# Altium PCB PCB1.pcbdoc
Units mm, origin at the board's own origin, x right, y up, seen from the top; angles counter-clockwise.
Board outline 137.83 x 75.64 mm, 4 copper layers (Top Layer, Inner1, Inner2, Bottom Layer); 54 components, 84 nets, 324 pads, 120 vias.
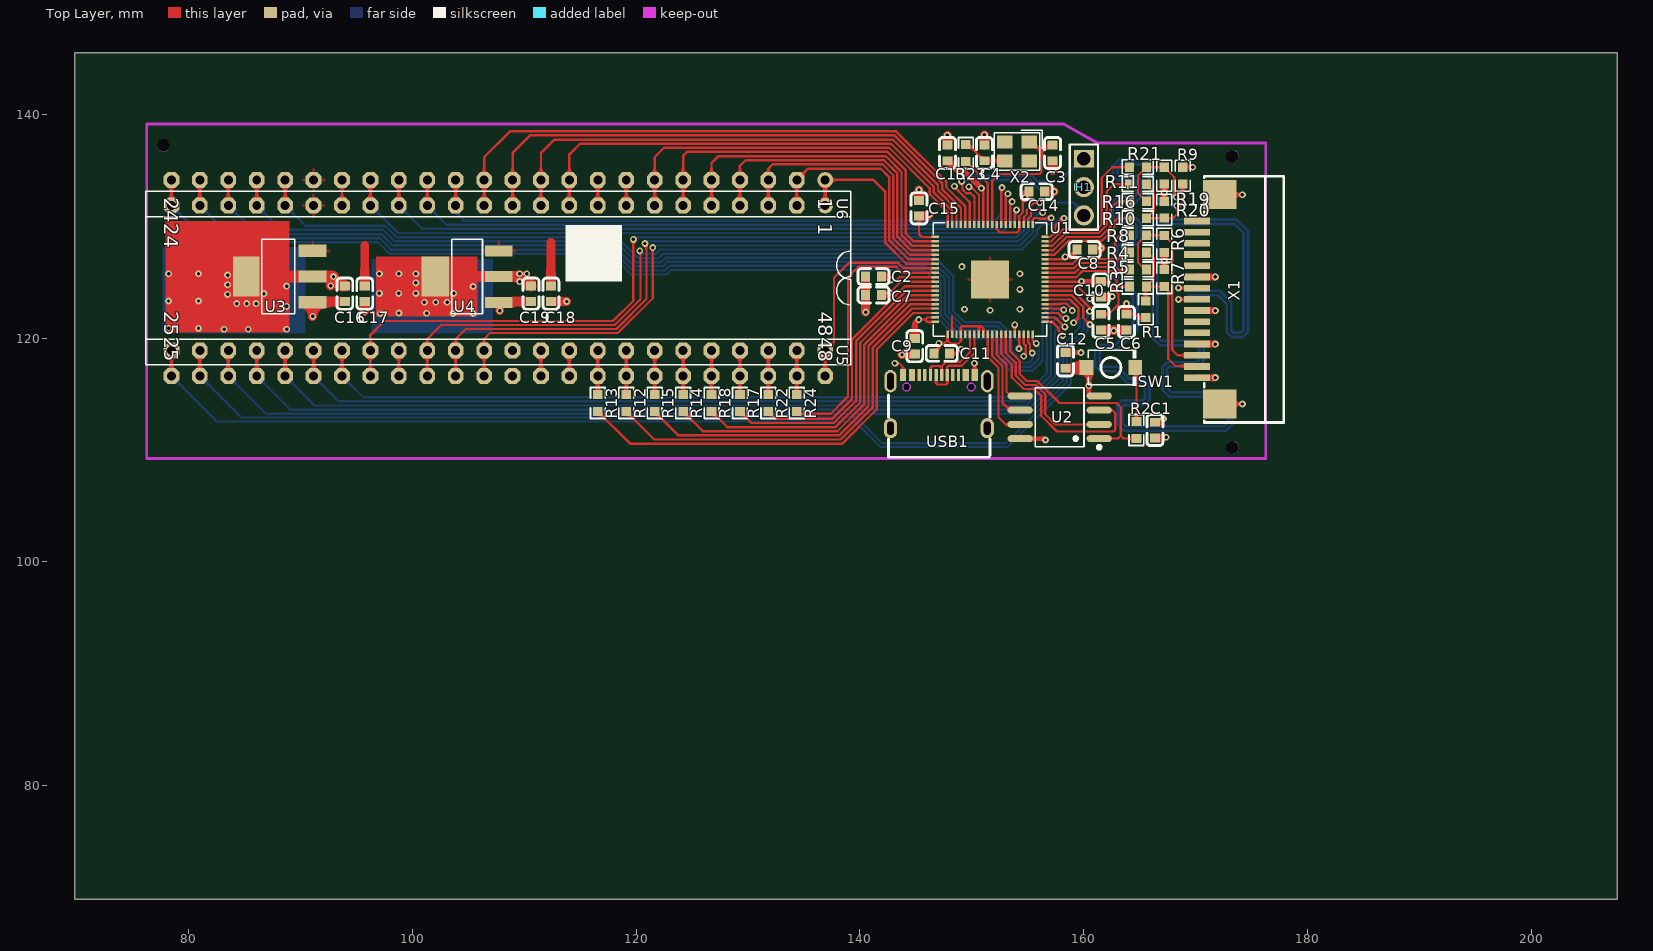
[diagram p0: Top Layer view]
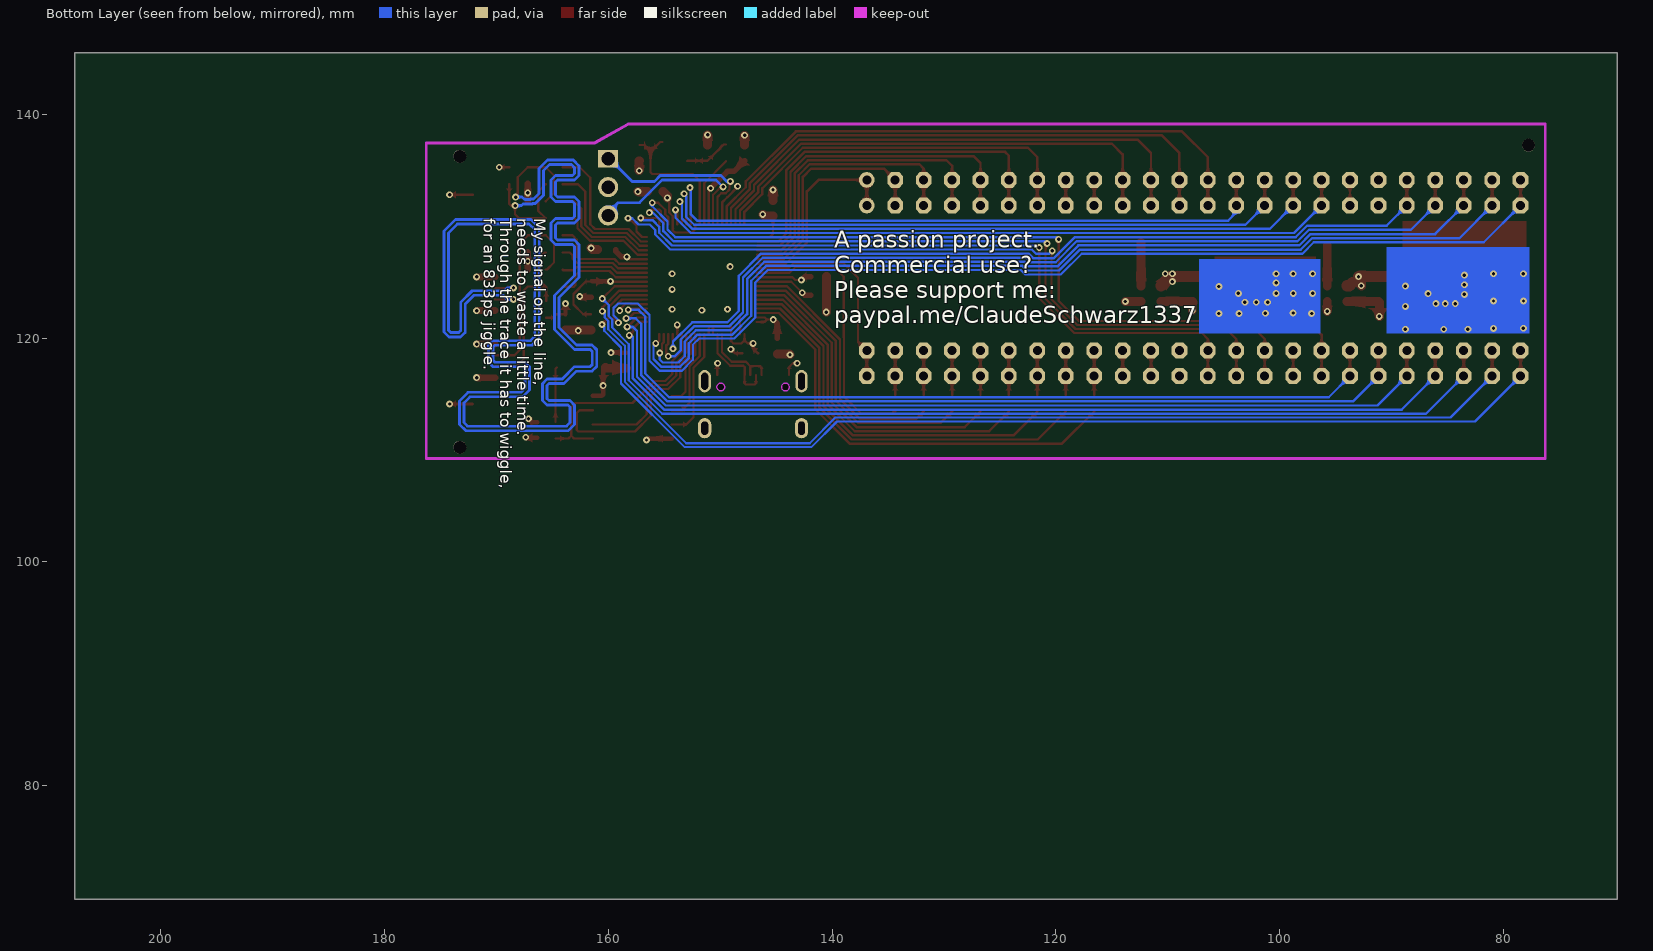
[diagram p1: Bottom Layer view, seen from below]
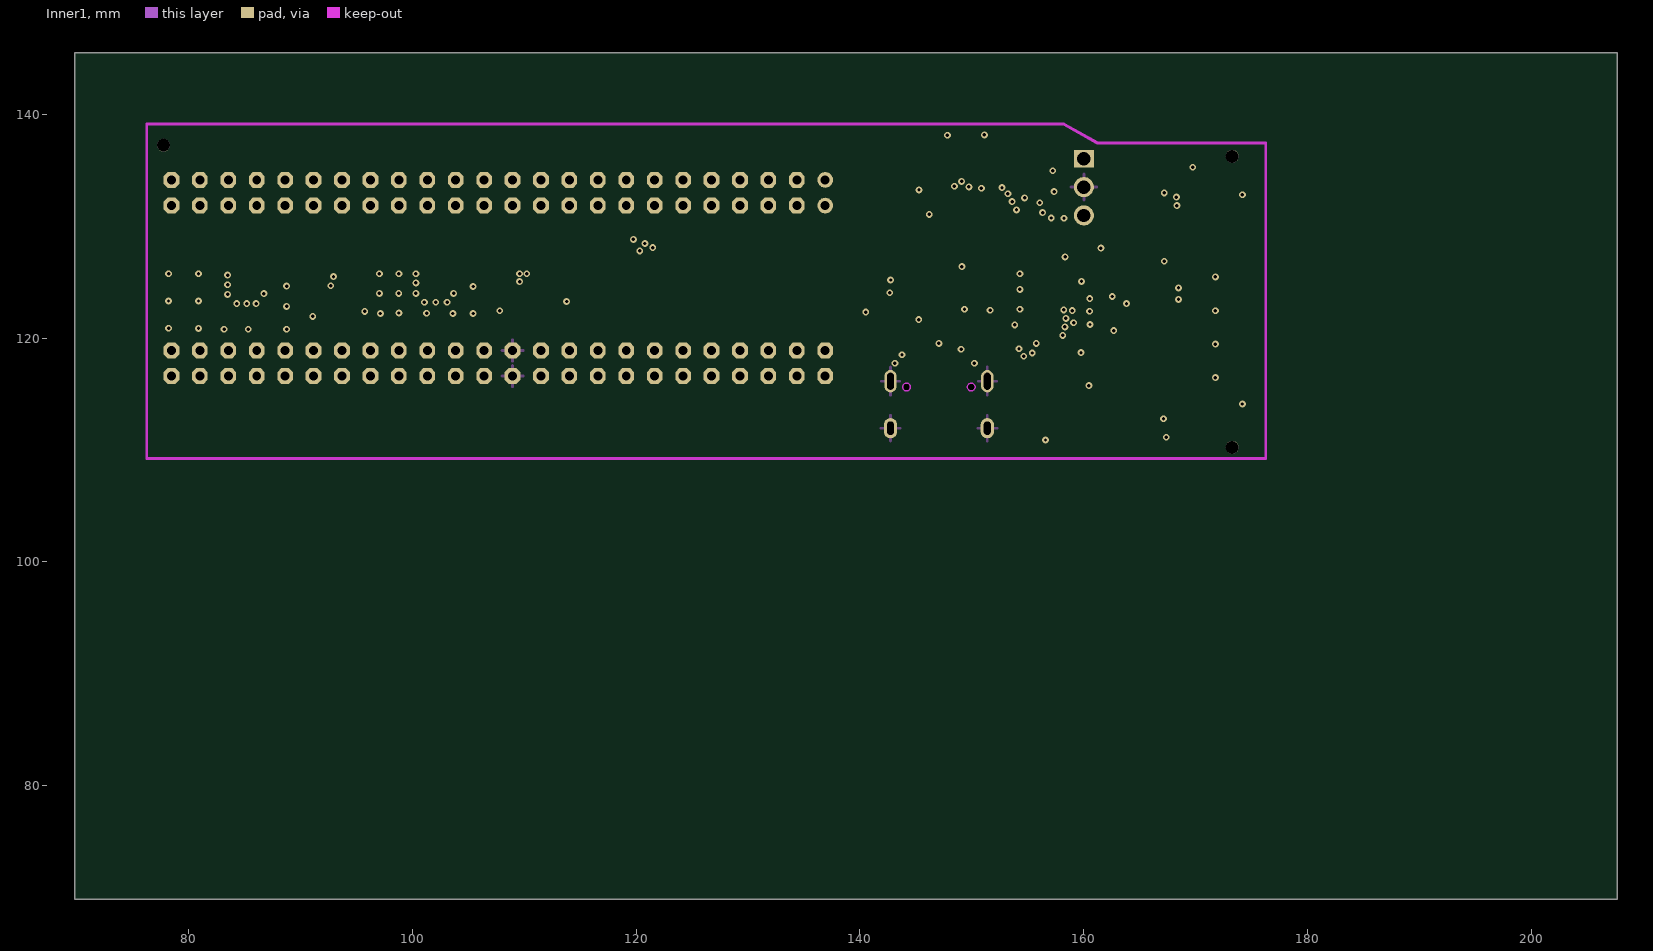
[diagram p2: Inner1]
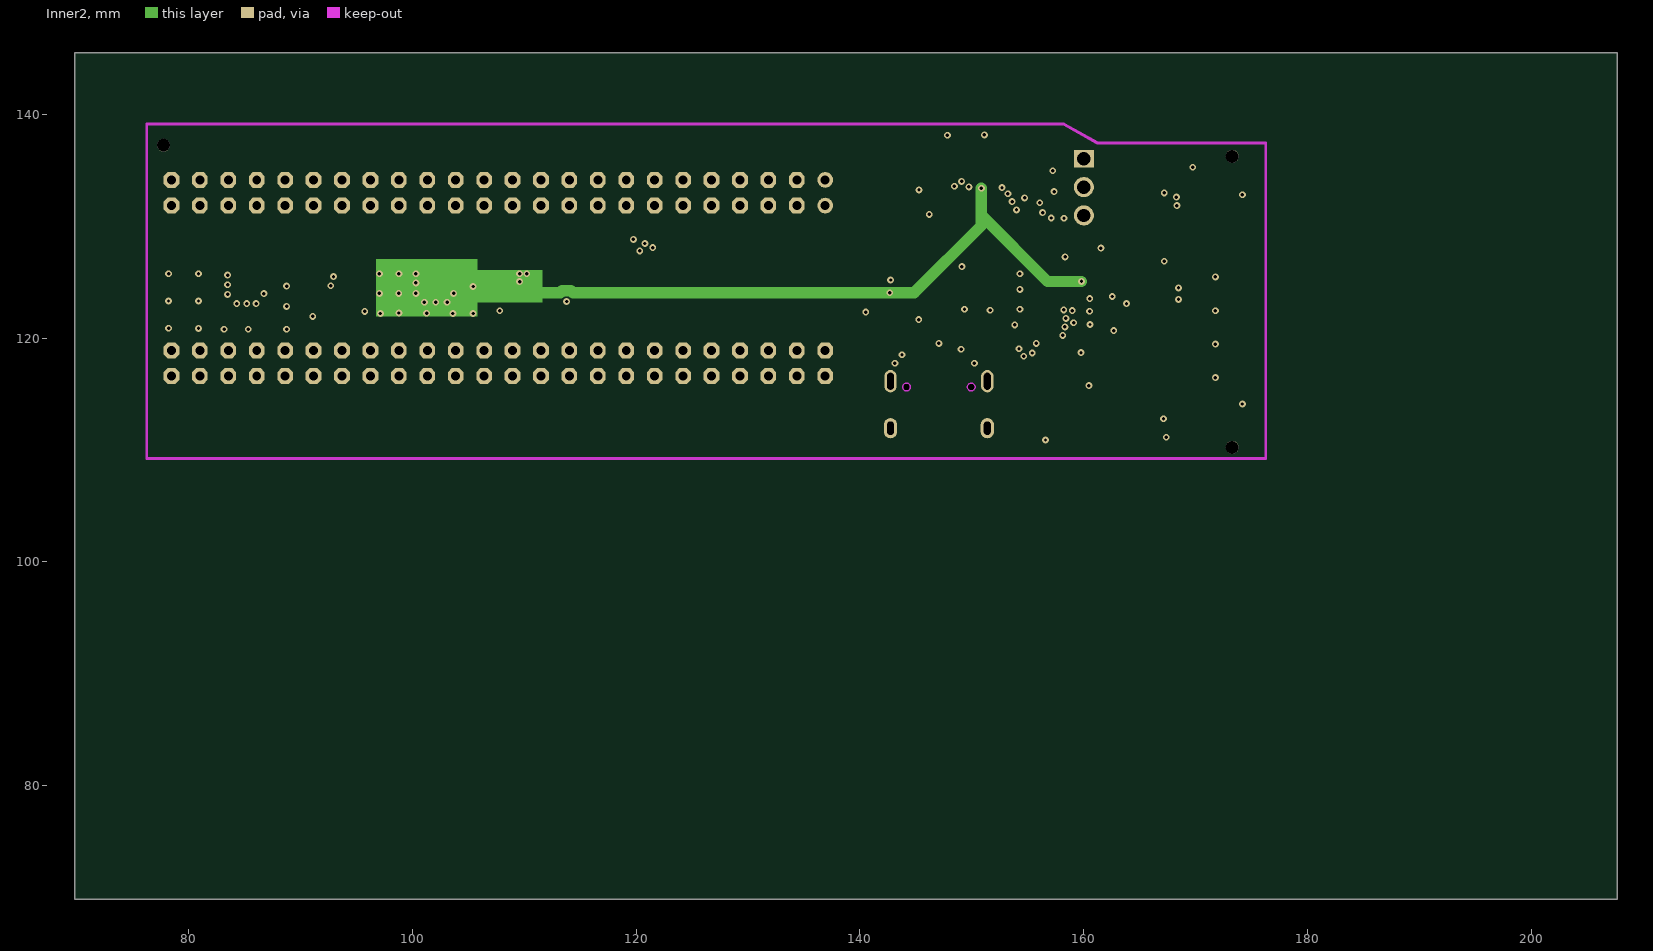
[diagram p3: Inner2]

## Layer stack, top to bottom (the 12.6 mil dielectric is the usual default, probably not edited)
Top Layer: signal copper (thickness not stored)
Dielectric: dielectric 0.32, FR-4, Dk 4.8
Inner1: signal copper (thickness not stored)
Dielectric: dielectric 0.32, FR-4, Dk 4.8
Inner2: signal copper (thickness not stored)
Dielectric: dielectric 0.32, FR-4, Dk 4.8
Bottom Layer: signal copper (thickness not stored)

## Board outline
207.677,69.85 69.85,69.85 69.85,145.489 207.677,145.489

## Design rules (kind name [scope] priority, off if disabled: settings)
BoardOutlineClearance copperThickness1oz [All] p0: genericclearance=0.254 ignorepadtopadclearanceinfootprint=FALSE except(0: Arc-SplitContinuation Track-SplitContinuation SMDPad-SplitContinuation THPad-SplitContinuation Via-SplitContinuation Fill-SplitContinuation Poly-SplitContinuation Region-SplitContinuation Text-SplitContinuation; 0.152: Track-CutoutEdge SMDPad-CutoutEdge THPad-CutoutEdge Via-CutoutEdge Region-CutoutEdge; 0.3: Track-OutlineEdge SMDPad-OutlineEdge THPad-OutlineEdge Via-OutlineEdge Fill-OutlineEdge Region-OutlineEdge Poly-OutlineEdge Text-OutlineEdge Fill-CutoutEdge)
BoardOutlineClearance copperThickness2oz [All] p0: genericclearance=0.254 ignorepadtopadclearanceinfootprint=FALSE except(0: Arc-SplitContinuation Track-SplitContinuation SMDPad-SplitContinuation THPad-SplitContinuation Via-SplitContinuation Fill-SplitContinuation Poly-SplitContinuation Region-SplitContinuation Text-SplitContinuation; 0.152: Track-CutoutEdge SMDPad-CutoutEdge THPad-CutoutEdge Via-CutoutEdge Region-CutoutEdge; 0.3: Track-OutlineEdge SMDPad-OutlineEdge THPad-OutlineEdge Via-OutlineEdge Fill-OutlineEdge Region-OutlineEdge Poly-OutlineEdge Text-OutlineEdge Fill-CutoutEdge)
Clearance copperThickness1oz [(InNet('DRD6') OR InNet('DRD5') OR InNet('DRD4') OR InNet('DRD3') OR InNet('DRD2') OR InNet('DRD1') OR InNet('DRD0') OR InNet('M1H') OR InNet('M0H') OR InNet('RGA8') OR InNet('RGA7') OR InNet('RGA6') OR InNet('RGA5') OR InNet('RGA4') OR InNet('RGA3') OR InNet('RGA2') OR InNet('RGA1') OR InNet('R0') OR InNet('R1') OR InNet('R2') OR InNet('R3') OR InNet('B0') OR InNet('B1') OR InNet('B2') OR InNet('B3') OR InNet('G0') OR InNet('G1') OR InNet('G2') OR InNet('G3') OR InNet('M0V') OR InNet('M1V') OR InNet('DRD15') OR InNet('DRD14') OR InNet('DRD13') OR InNet('DRD12') OR InNet('DRD11') OR InNet('DRD10') OR InNet('DRD9') OR InNet('DRD8') OR InNet('DRD7') OR InNet('$1N7209') OR InNet('$1N6294') OR InNet('$1N6291') OR InNet('$1N6288') OR InNet('$1N6285') OR InNet('$1N6303') OR InNet('$1N6300') OR InNet('$1N6306') OR InNet('$1N7218') OR InNet('$1N7223') OR InNet('$1N7228') OR InNet('$1N7233') OR InNet('$1N7238') OR InNet('$1N7248') OR InNet('$1N7253') OR InNet('BURST') OR InNet('VCC') OR InNet('BLANK') OR InNet('PIXELS') OR InNet('CDAC') OR InNet('7M') OR InNet('CCK') OR InNet('GND') OR InNet('$1N7405') OR InNet('$1N7425') OR InNet('$1N7416') OR InNet('$1N7453') OR InNet('VCC18') OR InNet('VCC33') OR InNet('$1N8365') OR InNet('$1N8305') OR InNet('$1N8373') OR InNet('$1N9909') OR InNet('$1N9901') OR InNet('USB_DM') OR InNet('USB_DP') OR InNet('SWCLK') OR InNet('SWDIO') OR InNet('$1N12175') OR InNet('CSI_CLK_P') OR InNet('CSI_CLK_N') OR InNet('CSI0_P') OR InNet('CSI0_N') OR InNet('$1N13618'))] p1: gap=0.178 ignorepadtopadclearanceinfootprint=FALSE except(0.152: Track-Track Track-SMDPad SMDPad-SMDPad Track-THPad SMDPad-THPad THPad-THPad Track-Via SMDPad-Via THPad-Via Via-Via SMDPad-Fill THPad-Fill Via-Fill Fill-Fill Track-Region SMDPad-Region THPad-Region Via-Region Region-Region Track-Poly SMDPad-Poly THPad-Poly Via-Poly Fill-Poly Region-Poly Poly-Poly Track-Text SMDPad-Text THPad-Text Via-Text Fill-Text Region-Text Poly-Text Text-Text; 0.175: Track-Hole SMDPad-Hole THPad-Hole Via-Hole Fill-Hole Region-Hole Poly-Hole Text-Hole Sheet-Hole; 0.3: Track-Fill Fill-Region Track-Sheet SMDPad-Sheet THPad-Sheet Via-Sheet Fill-Sheet Region-Sheet Poly-Sheet Text-Sheet)
Clearance copperThickness2oz [All] p1: gap=0.178 ignorepadtopadclearanceinfootprint=FALSE except(0.152: Track-SMDPad SMDPad-SMDPad Track-THPad SMDPad-THPad THPad-THPad Track-Via SMDPad-Via THPad-Via Via-Via SMDPad-Fill THPad-Fill Via-Fill Fill-Fill Track-Region SMDPad-Region THPad-Region Via-Region Region-Region Track-Poly SMDPad-Poly THPad-Poly Via-Poly Fill-Poly Region-Poly Poly-Poly Track-Text SMDPad-Text THPad-Text Via-Text Fill-Text Region-Text Poly-Text Text-Text; 0.175: Track-Hole SMDPad-Hole THPad-Hole Via-Hole Fill-Hole Region-Hole Poly-Hole Text-Hole Sheet-Hole; 0.203: Track-Track; 0.3: Track-Fill Fill-Region Track-Sheet SMDPad-Sheet THPad-Sheet Via-Sheet Fill-Sheet Region-Sheet Poly-Sheet Text-Sheet)
DiffPairsRouting differentialPair [All] p1: maxuncoupledlength=80 minlimit=5.9843 maxlimit=5.9843 mostfreqgap=5.9843 toplayer_minwidth=5 toplayer_prefwidth=10 toplayer_maxwidth=100 bottomlayer_minwidth=5 bottomlayer_prefwidth=10 bottomlayer_maxwidth=100 midlayer1_minwidth=5 midlayer1_prefwidth=10 midlayer1_maxwidth=100 midlayer2_minwidth=5 midlayer2_prefwidth=10 midlayer2_maxwidth=100
PasteMaskExpansion pasteMaskExpansion [All] p1: expansion=0
PlaneConnect innerPlane [All] p1: planeconnectstyle=Relief reliefexpansion=0.508 reliefentries=4 reliefconductorwidth=0.254 reliefairgap=0.254
PolygonConnect copperRegion [All] p1: connectstyle=Relief reliefentries=4 reliefconductorwidth=10 polygonreliefangle="90 Angle" airgapwidth=10
RoutingVias viaSize [All] p1: viastyle="Through Hole" holewidth=12.0078 minholewidth=11.811 maxholewidth=248.0316 width=24.0158 minwidth=19.685 maxwidth=393.7008
SolderMaskExpansion solderMaskExpansion [All] p1: useseparateexpansions=TRUE expansion=2.0079 expansionbottom=2.0079
Width copperThickness1oz [All] p1: maxlimit=100 minlimit=5 preferedwidth=10
Width copperThickness2oz [All] p1: maxlimit=100 minlimit=8 preferedwidth=10

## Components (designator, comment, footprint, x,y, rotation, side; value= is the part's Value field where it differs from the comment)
C1 "CC0603KRX7R9BB104" C0603 166.37,111.777 r90 top
C2 "CC0603KRX7R9BB104" C0603 141.224,125.493 r0 top
C3 "CL10C150JB8NNNC" C0603 157.226,136.542 r270 top
C4 "CL10C150JB8NNNC" C0603 151.13,136.542 r90 top
C5 "CL10A475KO8NNNC" C0603 161.544,121.429 r270 top
C6 "CL10A475KO8NNNC" C0603 163.83,121.429 r270 top
C7 "CC0603KRX7R9BB104" C0603 141.224,123.842 r180 top
C8 "CC0603KRX7R9BB104" C0603 160.094,127.906 r180 top
C9 "CC0603KRX7R9BB104" C0603 144.907,119.27 r270 top
C10 "CC0603KRX7R9BB104" C0603 161.544,124.35 r270 top
C11 "CC0603KRX7R9BB104" C0603 147.32,118.635 r180 top
C12 "CC0603KRX7R9BB104" C0603 158.369,118 r270 top
C13 "CC0603KRX7R9BB104" C0603 147.828,136.542 r90 top
C14 "CC0603KRX7R9BB104" C0603 155.807,133.084 r180 top
C15 "CC0603KRX7R9BB104" C0603 145.288,131.589 r90 top
C16 "CL10A106KP8NNNC" C0603 93.98,123.969 r90 top
C17 "CL10A106KP8NNNC" C0603 95.758,123.969 r90 top
C18 "CL10A106KP8NNNC" C0603 112.395,123.969 r90 top
C19 "CL10A106KP8NNNC" C0603 110.617,123.969 r90 top
H1 "2.54-1*3P针" HDR-TH_3P-P2.54-V-M-1 160.02,133.494 r270 top
R1 "0603WAF2201T5E_C4190" R0603 165.555,122.572 r270 top
R2 "0603WAF1000T5E" R0603 164.719,111.777 r90 top
R3 "0603WAF4700T5E" R0603 164.846,124.604 r0 top
R4 "0603WAF1500T5E" R0603 164.846,127.652 r0 top
R5 "0603WAF4700T5E" R0603 164.846,126.128 r0 top
R6 "0603WAF750JT5E" R0603 167.206,128.414 r90 top
R7 "0603WAF750JT5E" R0603 167.206,125.366 r270 top
R8 "0603WAF1500T5E" R0603 164.846,129.176 r0 top
R9 "0603WAF2201T5E_C4190" R0603 168.857,134.51 r90 top
R10 "0603WAF4700T5E" R0603 164.846,130.7 r0 top
R11 "0603WAF1500T5E" R0603 164.846,133.748 r0 top
R12 "0603WAF1000T5E" R0603 119.126,114.19 r90 top
R13 "0603WAF1000T5E" R0603 116.586,114.19 r90 top
R14 "0603WAF1000T5E" R0603 124.206,114.19 r90 top
R15 "0603WAF1000T5E" R0603 121.666,114.19 r90 top
R16 "0603WAF4700T5E" R0603 164.846,132.224 r0 top
R17 "0603WAF1000T5E" R0603 129.286,114.19 r90 top
R18 "0603WAF1000T5E" R0603 126.746,114.19 r90 top
R19 "0603WAF750JT5E" R0603 167.206,134.51 r90 top
R20 "0603WAF750JT5E" R0603 167.206,131.462 r270 top
R21 "0603WAF1500T5E" R0603 164.846,135.272 r0 top
R22 "0603WAF1000T5E" R0603 131.826,114.19 r90 top
R23 "0603WAF1001T5E" R0603 149.479,136.542 r90 top
R24 "0603WAF1000T5E" R0603 134.366,114.19 r90 top
SW1 "TS-1088-AR02016" SW-SMD_L3.9-W3.0-P4.45 162.433,117.365 r0 top
U1 "RP2350B_C42415655" QFN-80_L10.0-W10.0-P0.40-TL-EP3.4 151.638,125.239 r180 top locked
U2 "W25Q128JVSIQ" SOIC-8_L5.3-W5.3-P1.27-LS8.0-BL 157.861,112.92 r90 top
U3 "AMS1117-3.3_C6186" SOT-223-3_L6.5-W3.4-P2.30-LS7.0-BR 88.138,125.493 r0 top
U4 "AMS1117-1.8_C6185" SOT-223-4_L6.5-W3.5-P2.30-LS7.0-BR 104.902,125.493 r0 top
U5 "DENISE__DIP" DIP48-6 108.966,126.509 r180 top locked
U6 "DENISE__DIP" DIP48-6 108.966,124.223 r180 top locked
USB1 "TYPE-C 16PIN 2MD(073)" USB-C-SMD_TYPE-C-6PIN-2MD-073 147.066,114.317 r0 top
X1 "AFA07-S15FCA-00" FPC-SMD_15P-P1.00_JS_AFA07-S15XXX 171.143,123.461 r90 top
X2 "X322512MSB4SI" CRYSTAL-SMD_4P-L3.2-W2.5-BL 154.051,136.669 r180 top

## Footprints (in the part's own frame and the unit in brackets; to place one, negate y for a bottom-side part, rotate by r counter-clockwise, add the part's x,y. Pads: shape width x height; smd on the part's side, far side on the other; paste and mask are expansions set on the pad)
C0603 [mm]
  rect 0.8x0.9 smd: 1(-0.7,0) 2(0.7,0)
  silkscreen extent -1.39,-0.71 1.39,0.71
CRYSTAL-SMD_4P-L3.2-W2.5-BL [mm]
  rect 1.4x1.2 smd: 1(-1.1,-0.85) 2(1.1,-0.85) 3(1.1,0.85) 4(-1.1,0.85)
  silkscreen extent -2.26,-1.91 2.03,1.68
DIP48-6 [mm]
  round 1.4 hole 0.8: 1(-27.94,-7.62)
  oct 1.4x1.4 hole 0.8: 2(-25.4,-7.62) 3(-22.86,-7.62) 4(-20.32,-7.62) 5(-17.78,-7.62) 6(-15.24,-7.62) 7(-12.7,-7.62) 8(-10.16,-7.62) 9(-7.62,-7.62) 10(-5.08,-7.62) 11(-2.54,-7.62) 12(0,-7.62) 13(2.54,-7.62) 14(5.08,-7.62) 15(7.62,-7.62) 16(10.16,-7.62) 17(12.7,-7.62) 18(15.24,-7.62) 19(17.78,-7.62) 20(20.32,-7.62) 21(22.86,-7.62) 22(25.4,-7.62) 23(27.94,-7.62) 24(30.48,-7.62) 25(30.48,7.62) 26(27.94,7.62) 27(25.4,7.62) 28(22.86,7.62) 29(20.32,7.62) 30(17.78,7.62) 31(15.24,7.62) 32(12.7,7.62) 33(10.16,7.62) 34(7.62,7.62) 35(5.08,7.62) 36(2.54,7.62) 37(0,7.62) 38(-2.54,7.62) 39(-5.08,7.62) 40(-7.62,7.62) 41(-10.16,7.62) 42(-12.7,7.62) 43(-15.24,7.62) 44(-17.78,7.62) 45(-20.32,7.62) 46(-22.86,7.62) 47(-25.4,7.62) 48(-27.94,7.62)
  silkscreen extent -30.23,-6.6 32.77,6.6
FPC-SMD_15P-P1.00_JS_AFA07-S15XXX [mm]
  rect 0.6x2.3 smd: 1(-7,1.009) 2(-6,1.009) 3(-5,1.009) 4(-4,1.009) 5(-3,1.009) 6(-2,1.009) 7(-1,1.009) 8(0,1.009) 9(1,1.009) 10(2,1.01) 11(3,1.01) 12(4,1.01) 13(5,1.01) 14(6,1.009) 15(7,1.01)
  rect 2.6x3 smd: 16(9.352,-1.01) 17(-9.352,-1.01)
  silkscreen extent -11,-6.74 11,0.36
HDR-TH_3P-P2.54-V-M-1 [mm]
  rect 1.575x1.8 hole 1.2: 1(-2.54,0)
  round 1.8 hole 1.2: 2(0,0) 3(2.54,0)
  silkscreen extent -3.81,-1.27 3.81,1.27
QFN-80_L10.0-W10.0-P0.40-TL-EP3.4 [mm]
  rect 0.665x0.22 smd: 1(-4.908,3.8) 2(-4.908,3.4) 3(-4.908,3) 4(-4.908,2.6) 5(-4.908,2.2) 6(-4.908,1.8) 7(-4.908,1.4) 8(-4.908,1) 9(-4.908,0.6) 10(-4.908,0.2) 11(-4.908,-0.2) 12(-4.908,-0.6) 13(-4.908,-1) 14(-4.908,-1.4) 15(-4.908,-1.8) 16(-4.908,-2.2) 17(-4.908,-2.6) 18(-4.908,-3) 19(-4.908,-3.4) 20(-4.908,-3.8) 41(4.908,-3.8) 42(4.908,-3.4) 43(4.908,-3) 44(4.908,-2.6) 45(4.908,-2.2) 46(4.908,-1.8) 47(4.908,-1.4) 48(4.908,-1) 49(4.908,-0.6) 50(4.908,-0.2) 51(4.908,0.2) 52(4.908,0.6) 53(4.908,1) 54(4.908,1.4) 55(4.908,1.8) 56(4.908,2.2) 57(4.908,2.6) 58(4.908,3) 59(4.908,3.4) 60(4.908,3.8)
  rect 0.22x0.665 smd: 21(-3.8,-4.908) 22(-3.4,-4.908) 23(-3,-4.908) 24(-2.6,-4.908) 25(-2.2,-4.908) 26(-1.8,-4.908) 27(-1.4,-4.908) 28(-1,-4.908) 29(-0.6,-4.908) 30(-0.2,-4.908) 31(0.2,-4.908) 32(0.6,-4.908) 33(1,-4.908) 34(1.4,-4.908) 35(1.8,-4.908) 36(2.2,-4.908) 37(2.6,-4.908) 38(3,-4.908) 39(3.4,-4.908) 40(3.8,-4.908) 61(3.8,4.908) 62(3.4,4.908) 63(3,4.908) 64(2.6,4.908) 65(2.2,4.908) 66(1.8,4.908) 67(1.4,4.908) 68(1,4.908) 69(0.6,4.908) 70(0.2,4.908) 71(-0.2,4.908) 72(-0.6,4.908) 73(-1,4.908) 74(-1.4,4.908) 75(-1.8,4.908) 76(-2.2,4.908) 77(-2.6,4.908) 78(-3,4.908) 79(-3.4,4.908) 80(-3.8,4.908)
  rect 3.4x3.4 smd: 81(0,0)
  silkscreen extent -5.47,-5.08 5.08,5.08
R0603 [mm]
  rect 0.806x0.864 smd: 1(-0.753,0) 2(0.753,0)
  silkscreen extent -1.39,-0.66 1.39,0.66
SOIC-8_L5.3-W5.3-P1.27-LS8.0-BL [mm]
  oval 0.63x2.25 smd: 1(-1.905,-3.53) 2(-0.635,-3.53) 3(0.635,-3.53) 4(1.905,-3.53) 5(1.905,3.53) 6(0.635,3.53) 7(-0.635,3.53) 8(-1.905,3.53)
  silkscreen extent -2.82,-3.68 2.64,2.18
SOT-223-3_L6.5-W3.4-P2.30-LS7.0-BR [mm]
  rect 2.5x1.1 smd: 1(2.97,-2.3) 2(2.97,0) 3(2.97,2.3)
  rect 2.34x3.6 smd: 4(-2.97,0)
  silkscreen extent -1.57,-3.33 1.37,3.33
SOT-223-4_L6.5-W3.5-P2.30-LS7.0-BR [mm]
  rect 2.47x0.98 smd: 1(2.835,-2.3) 2(2.835,0) 3(2.835,2.3)
  rect 2.47x3.6 smd: 4(-2.835,0)
  silkscreen extent -1.37,-3.33 1.37,3.33
SW-SMD_L3.9-W3.0-P4.45 [mm]
  rect 1.23x1.36 smd: 1(-2.185,0) 2(2.185,0)
  silkscreen extent -2.03,-1.62 2.25,1.62
USB-C-SMD_TYPE-C-6PIN-2MD-073 [mm]
  rect 0.55x1.1 smd: 1(-3.2,2.375) 2(-2.4,2.375) 11(2.4,2.375) 12(3.2,2.375)
  rect 0.3x1.1 smd: 3(-1.75,2.375) 4(-1.25,2.375) 5(-0.75,2.375) 6(-0.25,2.375) 7(0.25,2.375) 8(0.75,2.375) 9(1.25,2.375) 10(1.75,2.375)
  oval 1.2x1.8 hole 0.6 slot 1.2 at 90 deg: 13(-4.325,-2.375) 14(4.325,-2.375)
  oval 1.1x2 hole 0.6 slot 1.5 at 90 deg: 13(-4.325,1.825) 14(4.325,1.825)
  Board Outline Layer circle w0.005: c-2.89,1.305 r0.35
  Board Outline Layer circle w0.005: c2.89,1.305 r0.35
  Board Outline Layer region: -2.54,1.305 -2.575,1.153 -2.672,1.031 -2.812,0.964 -2.968,0.964 -3.108,1.031 -3.205,1.153 -3.24,1.305 -3.24,1.305 -3.205,1.457 -3.108,1.579 -2.968,1.646 -2.812,1.646 -2.672,1.579 -2.575,1.457 -2.54,1.305
  Board Outline Layer region: 3.24,1.305 3.205,1.153 3.108,1.031 2.968,0.964 2.812,0.964 2.672,1.031 2.575,1.153 2.54,1.305 2.54,1.305 2.575,1.457 2.672,1.579 2.812,1.646 2.968,1.646 3.108,1.579 3.205,1.457 3.24,1.305
  Multi-Layer board cut-out: -2.54,1.305 -2.575,1.153 -2.672,1.031 -2.812,0.964 -2.968,0.964 -3.108,1.031 -3.205,1.153 -3.24,1.305 -3.24,1.305 -3.205,1.457 -3.108,1.579 -2.968,1.646 -2.812,1.646 -2.672,1.579 -2.575,1.457 -2.54,1.305
  Multi-Layer board cut-out: 3.24,1.305 3.205,1.153 3.108,1.031 2.968,0.964 2.812,0.964 2.672,1.031 2.575,1.153 2.54,1.305 2.54,1.305 2.575,1.457 2.672,1.579 2.812,1.646 2.968,1.646 3.108,1.579 3.205,1.457 3.24,1.305
  silkscreen extent -4.5,-4.97 4.57,0.6

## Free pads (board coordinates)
  round 1.152 hole 1.152 unplated: 1(77.774,137.237) 1(173.274,110.237) 1(173.274,136.237)

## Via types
v1: diameter 0.61, hole 0.305, Top Layer to Bottom Layer, 120 vias

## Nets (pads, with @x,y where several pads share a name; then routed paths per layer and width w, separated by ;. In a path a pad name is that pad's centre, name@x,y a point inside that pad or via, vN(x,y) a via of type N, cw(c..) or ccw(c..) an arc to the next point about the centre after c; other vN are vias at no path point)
7M: U1.22 U5.35 U6.35 | length 66.4
  Top Layer w0.2: U5.35 103.886,119.905 104.796,120.815 118.25,120.815 120.943,123.508 120.943,128.301 v1(120.793,128.452)
  Top Layer w0.216: U6.35 U5.35 ; U1.22 155.038,130.665 155.293,130.92 155.293,131.32 155.446,131.473 156.072,131.473 v1(156.337,131.208)
  Bottom Layer w0.216: v1(120.793,128.452) 120.989,128.648 154.171,128.648 155.08,129.557 155.08,130.256 156.032,131.208 v1(156.337,131.208)
$1N6285: R14.1 U1.55 | length 31.2
  Top Layer w0.216: R14.1 125.974,111.669 137.979,111.669 140.403,114.093 140.403,119.427 144.415,123.439 U1.55@146.685,123.439
$1N6288: R18.1 U1.54 | length 28.5
  Top Layer w0.216: R18.1 128.146,112.037 137.826,112.037 140.035,114.245 140.035,119.579 144.295,123.839 U1.54@146.685,123.839
$1N6291: R17.1 U1.53 | length 25.9
  Top Layer w0.216: R17.1 130.317,112.405 137.674,112.405 139.667,114.398 139.667,119.732 144.174,124.239 U1.53@146.685,124.239
$1N6294: R22.1 U1.52 | length 23.2
  Top Layer w0.216: R22.1 132.489,112.773 137.521,112.773 139.298,114.55 139.298,119.884 144.053,124.639 U1.52@146.685,124.639
$1N6300: R12.1 U1.57 | length 36.6
  Top Layer w0.216: R12.1 121.631,110.932 138.284,110.932 141.14,113.788 141.14,119.122 144.657,122.639 U1.57@146.685,122.639
$1N6303: R15.1 U1.56 | length 33.9
  Top Layer w0.216: R15.1 123.802,111.3 138.132,111.3 140.771,113.94 140.771,119.274 144.536,123.039 U1.56@146.685,123.039
$1N6306: R13.1 U1.58 | length 39.2
  Top Layer w0.216: R13.1 119.459,110.564 138.437,110.564 141.508,113.635 141.508,118.969 144.778,122.239 U1.58@146.685,122.239
$1N7209: R24.1 U1.49 | length 24.4
  Top Layer w0.2: R24.1 134.493,113.437 134.693,113.237 137.396,113.237 138.938,114.778 138.938,120.034 138.962,120.058 138.962,125.469 139.875,126.382 143.266,126.382 143.809,125.839 U1.49
$1N7218: R3.1 U1.11 | length 8.9
  Top Layer w0.2: U1.11 159.331,125.439 159.893,126.001 162.56,126.001 162.941,125.62 162.941,124.731 163.082,124.59 164.078,124.59 R3.1
$1N7223: R5.1 U1.12 | length 7.9
  Top Layer w0.2: U1.12 159.233,125.839 159.747,126.353 162.843,126.353 163.136,126.06 164.024,126.06 R5.1
$1N7228: R4.1 U1.13 | length 8.3
  Top Layer w0.2: U1.13 159.134,126.239 159.601,126.706 162.786,126.706 163.195,127.115 163.195,127.398 163.449,127.652 R4.1
$1N7233: R8.1 U1.14 | length 9.5
  Top Layer w0.2: U1.14 159.036,126.639 159.455,127.058 162.601,127.058 162.814,127.271 162.814,128.795 163.195,129.176 R8.1
$1N7238: R10.1 U1.16 | length 9.3
  Top Layer w0.2: U1.16 157.392,127.439 158.639,128.685 161.635,128.685 162.766,129.817 162.766,130.432 163.035,130.7 R10.1
$1N7248: R11.1 U1.18 | length 11.6
  Top Layer w0.2: U1.18 157.196,128.239 158.347,129.39 161.343,129.39 162.062,130.109 162.062,133.105 162.705,133.748 R11.1
$1N7253: R21.1 U1.19 | length 12.7
  Top Layer w0.2: U1.19 157.097,128.639 158.201,129.743 161.197,129.743 161.623,130.168 161.623,134.335 162.56,135.272 R21.1
$1N7405: U1.71 U2.6 | length 8.4
  Top Layer w0.2: U1.71 151.838,118.404 152.752,117.489 152.752,114.19 153.387,113.555 U2.6
$1N7416: R2.1 U1.75 U2.1 | length 20.2
  Top Layer w0.2: U1.75 153.438,118.797 154.289,117.946 154.289,116.793 154.932,116.15 155.881,116.15 157.842,114.19 162.941,114.19 163.322,113.809 163.322,111.269 ; U2.1 163.068,111.015 163.322,111.269 ; R2.1 163.567,111.024 163.322,111.269
$1N7425: U1.74 U2.2 | length 14.4
  Top Layer w0.2: U1.74 153.038,118.699 153.937,117.8 153.937,116.647 154.786,115.798 155.735,115.798 156.562,114.971 156.562,113.203 157.48,112.285 U2.2
$1N7453: C3.1 U1.30 X2.1 | length 13.1
  Top Layer w0.2: U1.30 151.838,134.049 152.455,134.666 156.083,134.666 156.224,134.807 156.224,136.669 ; X2.1 155.374,137.519 156.224,136.669 ; C3.1 156.783,137.242 156.224,136.683 156.224,136.669
$1N8305: U1.72 U2.5 | length 6.9
  Top Layer w0.2: U1.72 152.238,118.502 153.105,117.635 153.105,115.206 153.486,114.825 U2.5
$1N8365: U1.70 U2.7 | length 10
  Top Layer w0.2: U1.70 151.438,118.305 152.4,117.343 152.4,112.92 153.035,112.285 U2.7
$1N8373: U1.73 U2.3 | length 19.6
  Top Layer w0.2: U1.73 152.638,118.6 153.584,117.654 153.584,116.501 154.64,115.446 155.589,115.446 156.21,114.825 156.21,113.057 157.617,111.65 162.687,111.65 162.828,111.791 162.828,113.301 162.574,113.555 U2.3
$1N9901: R23.1 U1.31 | length 6.5
  Top Layer w0.2: R23.1 151.438,133.83 U1.31
$1N9909: C4.1 R23.2 X2.3 | length 4.1
  Top Layer w0.2: R23.2 149.677,137.295 C4.1 152.928,135.842 X2.3
$1N12175: R2.2 SW1.2 | length 4.9
  Top Layer w0.2: SW1.2 164.719,117.264 R2.2
$1N13618: R16.1 U1.17 | length 10.3
  Top Layer w0.2: U1.17 157.294,127.839 158.493,129.038 161.489,129.038 162.414,129.963 162.414,131.57 163.068,132.224 R16.1
B0: U1.6 U5.24 U6.24 | length 103.8
  Top Layer w0.2: U1.6 156.621,123.439 156.629,123.446 158.772,123.446 159.536,122.683 159.536,121.8 v1(159.102,121.365)
  Top Layer w0.254: U6.24 U5.24
  Bottom Layer w0.2: U6.24 81.772,128.557 96.959,128.557 97.973,127.543 117.704,127.543 119.569,125.679 122.742,125.679 123.148,126.084 145.752,126.084 146.871,124.966 146.871,121.838 148.758,119.951 151.886,119.951 152.446,119.391 152.446,118.067 153.425,117.087 155.439,117.087 156.329,117.978 156.329,122.058 157.348,123.077 159.142,123.077 159.536,122.683 159.536,122.036 159.131,121.631 v1@159.131,121.302
B1: U1.7 U5.25 U6.25 | length 99.3
  Top Layer w0.216: U1.7 158.912,123.839 159.964,122.787 159.964,121.817 v1(160.568,121.213)
  Top Layer w0.254: U6.25 U5.25
  Bottom Layer w0.2: U6.25 82.55,112.539 139.573,112.539 141.859,110.253 153.183,110.253 158.877,115.947 158.877,119.162 160.363,120.649 160.363,121.009 v1(160.568,121.213)
B2: U1.8 U5.26 U6.26 | length 96.6
  Top Layer w0.216: U1.8 159.033,124.239 160.529,122.743 v1(160.529,122.401)
  Top Layer w0.254: U6.26 U5.26
  Bottom Layer w0.2: U6.26 84.738,112.891 139.719,112.891 142.005,110.605 153.037,110.605 158.523,116.091 158.523,119.307 160.011,120.795 160.011,121.514 160.324,121.827 160.324,122.196 v1(160.529,122.401)
B3: U1.9 U5.27 U6.27 | length 92.3
  Top Layer w0.2: U1.9 159.431,124.639 v1(160.543,123.527)
  Top Layer w0.254: U6.27 U5.27
  Bottom Layer w0.2: U6.27 86.925,113.244 155.177,113.244 158.17,116.237 158.17,119.453 159.659,120.941 159.659,121.66 159.972,121.973 159.972,122.956 v1(160.543,123.527)
BLANK: U1.23 U5.32 U6.32 | length 75.1
  Top Layer w0.216: U6.32 U5.32 96.266,120.286 97.507,121.527 117.954,121.527 119.766,123.339 v1(119.766,128.82) ; U1.23 154.638,130.785 154.92,131.068 154.92,131.468 155.55,132.097 v1(156.083,132.097)
  Bottom Layer w0.216: v1(119.766,128.82) 119.962,129.017 154.019,129.017 154.712,129.71 154.712,130.409 156.083,131.78 v1(156.083,132.097)
BURST: U5.18 U6.18 | length 2.3
  Top Layer w0.216: U6.18 U5.18
CCK: U1.21 U5.36 U6.36 | length 63.6
  Top Layer w0.2: U5.36 106.426,119.905 106.983,120.462 118.396,120.462 121.5,123.567 v1(121.5,128.083)
  Top Layer w0.216: U6.36 U5.36 ; U1.21 155.438,130.544 155.62,130.726 156.02,130.726 156.103,130.643 156.571,130.643 156.654,130.726 v1(157.099,130.726)
  Bottom Layer w0.216: v1(121.5,128.083) 121.687,128.27 154.314,128.27 155.448,129.404 155.448,129.938 156.02,130.51 156.883,130.51 v1(157.099,130.726)
CDAC: U1.20 U5.34 U6.34 | length 70.5
  Top Layer w0.2: U5.34 101.346,119.923 102.591,121.167 118.104,121.167 120.396,123.459 120.396,127.723 v1(120.331,127.788) ; U1.20 156.999,129.039 157.48,129.52 157.48,130.065 158.115,130.7 v1(158.242,130.7)
  Top Layer w0.216: U6.34 U5.34
  Bottom Layer w0.2: v1(120.331,127.788) 120.594,127.525 121.789,127.525 122.174,127.91 154.463,127.91 155.808,129.255 155.808,129.664 156.294,130.149 157.31,130.149 157.861,130.7 v1(158.242,130.7)
CSI0_N: R1.1 R3.2 R4.2 R7.2 X1.2 | length 16
  Top Layer w0.2: R1.1 165.555,124.56 R3.2 ; R4.2 165.735,127.652 166.255,127.132 166.255,125.592 166.243,125.58 166.243,125.248 R3.2 ; X1.2 170.103,117.492 168.222,117.492 167.566,118.147 167.566,124.252 R7.2 167.197,124.604 R3.2
CSI0_P: R5.2 R6.2 R8.2 X1.3 | length 18.3
  Top Layer w0.2: R5.2 165.481,126.128 164.846,126.763 164.846,128.423 R8.2 167.197,129.176 R6.2 167.919,128.454 167.919,118.938 168.396,118.461 X1.3
CSI_CLK_N: R9.1 R10.2 R11.2 R20.2 X1.8 | length 124.6
  Top Layer w0.2: R11.2 165.608,133.748 166.243,133.113 166.243,132.772 166.255,132.76 166.255,131.355 R10.2 167.197,130.7 R20.2 167.976,130.709 168.335,131.067 v1(168.335,131.834) 168.721,131.834 168.857,131.97 R9.1 ; v1(168.476,123.452) 170.125,123.452 X1.8
  Bottom Layer w0.25: v1(168.335,131.834) 167.78,131.834 167.623,131.991 166.798,131.991 166.775,132.014 166.532,132.014 165.788,132.759 165.788,134.979 165.261,135.505 163.308,135.505 163.025,135.222 163.025,134.706 163.202,134.529 164.709,134.529 165.121,134.117 165.121,132.613 164.709,132.201 163.202,132.201 163.025,132.024 163.025,130.854 163.202,130.677 164.709,130.677 165.121,130.265 165.121,128.761 164.709,128.349 163.202,128.349 163.025,128.172 163.025,125.583 164.814,123.794 164.814,120.767 163.014,118.967 161.615,118.967 161.438,118.79 161.438,117.62 161.615,117.443 163.014,117.443 164.123,116.333 165.471,116.333 165.883,115.921 165.883,114.418 165.471,114.005 163.603,114.005 163.426,113.829 163.426,112.448 163.748,112.126 172.574,112.126 172.9,112.452 172.9,114.211 172.363,114.748 167.664,114.748 167.058,115.354 167.058,117.427 167.47,117.839 170.13,117.839 170.307,118.016 170.307,119.186 170.13,119.363 166.798,119.363 166.169,119.993 166.169,129.851 166.912,130.594 173.662,130.594 174.69,129.566 174.69,120.531 174.247,120.088 173.206,120.088 172.794,120.501 172.794,123.02 171.992,123.821 169.4,123.821 169.031,123.452 v1(168.476,123.452)
CSI_CLK_P: R16.2 R19.2 R21.2 X1.9 | length 123.3
  Top Layer w0.2: R16.2 164.846,132.977 164.846,134.51 165.599,135.263 R21.2 167.197,135.272 R19.2 168.095,134.374 168.095,132.785 v1(168.284,132.596) ; v1(168.476,124.477) 170.118,124.477 X1.9
  Bottom Layer w0.25: v1(168.284,132.596) 167.729,132.596 167.549,132.416 167.47,132.416 167.447,132.393 166.965,132.393 166.941,132.416 166.699,132.416 166.19,132.925 166.19,135.145 165.428,135.907 163.142,135.907 162.623,135.389 162.623,134.539 163.036,134.127 164.542,134.127 164.719,133.95 164.719,132.78 164.542,132.603 163.036,132.603 162.623,132.191 162.623,130.687 163.036,130.275 164.542,130.275 164.719,130.098 164.719,128.928 164.542,128.751 163.036,128.751 162.623,128.339 162.623,125.416 164.412,123.628 164.412,120.933 162.847,119.369 161.448,119.369 161.036,118.957 161.036,117.453 161.448,117.041 162.847,117.041 163.957,115.931 165.304,115.931 165.481,115.755 165.481,114.584 165.304,114.407 163.436,114.407 163.024,113.995 163.024,112.276 163.576,111.724 172.741,111.724 173.302,112.285 173.302,114.378 172.53,115.15 167.831,115.15 167.46,115.521 167.46,117.26 167.637,117.437 170.297,117.437 170.709,117.849 170.709,119.353 170.297,119.765 166.965,119.765 166.571,120.159 166.571,129.684 167.079,130.192 173.495,130.192 174.288,129.4 174.288,120.697 174.081,120.49 173.373,120.49 173.196,120.667 173.196,123.186 172.159,124.223 169.285,124.223 169.031,124.477 v1(168.476,124.477)
DRD0: U1.40 U5.7 U6.7 | length 34.6
  Top Layer w0.216: U5.7 121.666,136.161 122.504,136.999 142.622,136.999 146.247,133.374 146.247,132.864 147.838,131.274 U1.40
  Top Layer w0.254: U6.7 U5.7
DRD1: U1.42 U5.6 U6.6 | length 33.7
  Top Layer w0.216: U5.6 124.206,136.288 124.549,136.631 142.469,136.631 144.094,135.006 144.094,129.367 144.822,128.639 U1.42@146.685,128.639
  Top Layer w0.254: U6.6 U5.6
DRD2: U1.43 U5.5 U6.5 | length 30.6
  Top Layer w0.216: U5.5 126.746,135.653 127.356,136.263 142.317,136.263 143.726,134.854 143.726,129.214 144.701,128.239 U1.43@146.685,128.239
  Top Layer w0.254: U6.5 U5.5
DRD3: U1.44 U5.4 U6.4 | length 27.8
  Top Layer w0.216: U5.4 129.286,135.399 129.781,135.894 142.164,135.894 143.358,134.701 143.358,129.062 144.58,127.839 U1.44@146.685,127.839
  Top Layer w0.254: U6.4 U5.4
DRD4: U1.45 U5.3 U6.3 | length 25
  Top Layer w0.216: U5.3 131.826,135.145 132.207,135.526 142.012,135.526 142.989,134.548 142.989,128.909 144.459,127.439 U1.45@146.685,127.439
  Top Layer w0.254: U6.3 U5.3
DRD5: U1.46 U5.2 U6.2 | length 21.7
  Top Layer w0.216: U5.2 135.382,135.145 141.872,135.145 142.621,134.396 142.621,128.756 144.338,127.039 U1.46@146.685,127.039
  Top Layer w0.254: U6.2 U5.2
DRD6: U1.47 U5.1 U6.1 | length 17.8
  Top Layer w0.216: U5.1 141.224,134.129 142.253,133.1 142.253,128.528 144.142,126.639 U1.47@146.685,126.639
  Top Layer w0.305: U6.1 U5.1
DRD7: U1.48 U5.48 U6.48 | length 18.9
  Top Layer w0.2: 139.035,126.734 143.412,126.734 143.907,126.239 U1.48
  Top Layer w0.216: U5.48 137.689,119.672 137.689,125.387 139.035,126.733
  Top Layer w0.254: U6.48 U5.48
DRD8: R24.2 U5.47 U6.47 | length 3.9
  Top Layer w0.216: R24.2 U6.47
  Top Layer w0.254: U6.47 U5.47
DRD9: R22.2 U5.46 U6.46 | length 3.9
  Top Layer w0.216: R22.2 U6.46
  Top Layer w0.254: U6.46 U5.46
DRD10: R17.2 U5.45 U6.45 | length 3.9
  Top Layer w0.216: R17.2 U6.45
  Top Layer w0.254: U6.45 U5.45
DRD11: R18.2 U5.44 U6.44 | length 3.9
  Top Layer w0.216: R18.2 U6.44
  Top Layer w0.254: U6.44 U5.44
DRD12: R14.2 U5.43 U6.43 | length 4
  Top Layer w0.216: R14.2 U6.43
  Top Layer w0.254: U5.43@124.19,118.905 U5.43 U6.43
DRD13: R15.2 U5.42 U6.42 | length 3.9
  Top Layer w0.216: R15.2 U6.42
  Top Layer w0.254: U6.42 U5.42
DRD14: R12.2 U5.41 U6.41 | length 3.9
  Top Layer w0.216: R12.2 U6.41
  Top Layer w0.254: U6.41 U5.41
DRD15: R13.2 U5.40 U6.40 | length 3.9
  Top Layer w0.216: R13.2 U6.40
  Top Layer w0.254: U6.40 U5.40
G0: U1.1 U5.28 U6.28 | length 82.7
  Top Layer w0.216: U1.1 157.216,121.439 157.762,120.893 157.762,120.606 v1(158.134,120.234)
  Top Layer w0.254: U6.28 U5.28
  Bottom Layer w0.216: U6.28 89.105,113.604 155.028,113.604 157.81,116.387 157.81,120.108 157.936,120.234 v1(158.134,120.234)
G1: U1.2 U5.29 U6.29 | length 80.5
  Top Layer w0.216: U1.2 157.451,121.839 158.294,120.996 v1(158.327,120.996)
  Top Layer w0.254: U6.29 U5.29
  Bottom Layer w0.216: U6.29 91.277,113.972 154.875,113.972 157.442,116.539 157.442,120.629 157.809,120.996 v1(158.327,120.996)
G2: U1.3 U5.30 U6.30 | length 78.3
  Top Layer w0.216: U1.3 157.7,122.239 158.236,121.703 158.363,121.703 v1(158.418,121.758)
  Top Layer w0.254: U6.30 U5.30
  Bottom Layer w0.216: U6.30 93.448,114.341 154.723,114.341 157.074,116.692 157.074,121.277 157.555,121.758 v1(158.418,121.758)
G3: U1.4 U5.31 U6.31 | length 75.5
  Top Layer w0.216: U1.4 158.099,122.639 v1(158.218,122.52)
  Top Layer w0.254: U6.31 U5.31
  Bottom Layer w0.216: U6.31 95.62,114.709 154.57,114.709 156.705,116.844 156.705,121.924 157.301,122.52 v1(158.218,122.52)
GND: C1.1 C2.1 C3.2 C4.2 C5.2 C6.2 C7.2 C8.1 C9.2 C10.2 C11.1 C12.2 C13.2 C14.1 C15.2 C16.1 C17.1 C18.1 C19.1 H1.2 R6.1 R7.1 R19.1 R20.1 SW1.1 U1.62 U1.81 U2.4 U3.1 U4.1 U5.37 U6.37 USB1.1 USB1.12 USB1.13 USB1.14 X1.1 X1.4 X1.7 X1.10 X1.16 X1.17 | length 48.6
  Top Layer w0.2: v1(143.129,117.746) 143.51,117.746 143.866,117.39 USB1.1 ; C11.1 148.677,118.635 v1(149.047,119.005) ; U1.62 148.238,121.937 ; v1(150.241,117.746) 150.266,117.721 USB1.12
  Top Layer w0.25: X1.17 v1(174.191,114.109) ; X1.16 v1(174.191,132.813)
  Top Layer w0.4: SW1.1 160.465,117.148 v1(160.465,115.751) 160.465,114.93 160.57,114.825 U2.4 ; C1.1 167.321,111.077 v1(167.386,111.142)
  Top Layer w0.5: C10.2 162.495,123.65 v1(162.56,123.715)
  Top Layer w0.6: R7.1 v1(167.206,126.857) R6.1 ; R20.1 v1(167.206,132.975) R19.1 ; X1.10 v1(171.778,125.461) ; X1.1 v1(171.778,116.461) ; X1.4 v1(171.778,119.461) ; X1.7 171.762,122.461 v1(171.778,122.445)
  Top Layer w0.8: v1(91.108,121.937) U3.1 91.184,123.269 C16.1 ; v1(95.758,122.38) C17.1 ; v1(107.823,122.445) 107.823,123.107 U4.1 107.813,123.269 C19.1 ; C18.1 v1(113.792,123.269) ; v1(140.524,122.318) C7.2 C2.1 ; v1(143.764,118.508) 143.826,118.57 C9.2 ; C15.2 v1(145.288,133.24) ; C13.2 v1(147.828,138.123) ; C4.2 v1(151.13,138.153) ; C14.1 v1(157.357,133.084) ; C3.2 157.245,135.823 v1(157.245,134.954) ; C12.2 160.183,117.3 SW1.1 ; C8.1@160.981,127.929 161.44,127.929 v1(161.544,128.033) ; C5.2 v1@162.625,120.729 ; v1(162.687,120.667) v1@162.625,120.729 ; C6.2 v1@162.625,120.729
  other v1: 151.638,122.485 149.352,122.572 154.305,122.572 154.305,124.35 154.305,125.747 149.117,126.382
M0H: U5.9 U6.9 | length 2.3
  Top Layer w0.254: U6.9 U5.9
M0V: U5.38 U6.38 | length 2.3
  Top Layer w0.254: U6.38 U5.38
M1H: U5.8 U6.8 | length 2.3
  Top Layer w0.254: U6.8 U5.8
M1V: U5.39 U6.39 | length 2.3
  Top Layer w0.254: U6.39 U5.39
PIXELS: U5.33 U6.33 | length 2.3
  Top Layer w0.216: U6.33 U5.33
R0: U1.77 U5.20 U6.20 | length 77
  Top Layer w0.216: v1(154.223,119.04) 154.238,119.055 U1.77
  Top Layer w0.254: U6.20 U5.20
  Bottom Layer w0.216: U6.20 90.445,130.044 97.544,130.044 98.571,129.017 118.303,129.017 120.176,127.144 122.042,127.144 122.448,127.55 146.359,127.55 148.336,125.573 148.336,122.445 149.365,121.416 152.493,121.416 154.223,119.685 v1(154.223,119.04)
R1: U1.78 U5.21 U6.21 | length 81.2
  Top Layer w0.216: U1.78 154.638,119.519 154.813,119.344 154.813,118.635 154.642,118.464 v1(154.642,118.381)
  Top Layer w0.254: U6.21 U5.21
  Bottom Layer w0.216: U6.21 88.273,129.676 97.391,129.676 98.419,128.648 118.151,128.648 120.023,126.776 122.24,126.776 122.646,127.181 146.207,127.181 147.968,125.42 147.968,122.292 149.212,121.048 152.34,121.048 153.543,119.845 153.543,118.889 154.051,118.381 v1(154.642,118.381)
R2: U1.79 U5.22 U6.22 | length 85.4
  Top Layer w0.216: U1.79 155.038,119.639 155.207,119.47 155.207,118.818 155.358,118.667 v1(155.404,118.667)
  Top Layer w0.254: U6.22 U5.22
  Bottom Layer w0.216: U6.22 86.123,129.286 97.26,129.286 98.266,128.28 117.998,128.28 119.871,126.407 122.396,126.407 122.802,126.813 146.054,126.813 147.599,125.268 147.599,122.14 149.06,120.68 152.187,120.68 153.175,119.693 153.175,118.368 153.727,117.816 155.137,117.816 155.404,118.083 v1(155.404,118.667)
R3: U1.80 U5.23 U6.23 | length 88.9
  Top Layer w0.216: U1.80 155.438,119.778 155.692,119.524 v1(155.772,119.524)
  Top Layer w0.254: U6.23 U5.23
  Bottom Layer w0.216: U6.23 83.951,128.918 97.108,128.918 98.122,127.904 117.854,127.904 119.718,126.039 122.593,126.039 122.999,126.445 145.902,126.445 147.231,125.115 147.231,121.987 148.907,120.311 152.035,120.311 152.806,119.54 152.806,118.216 153.574,117.448 155.29,117.448 155.969,118.127 155.969,119.327 v1(155.772,119.524)
RGA1: U1.25 U5.17 U6.17 | length 63.7
  Top Layer w0.216: U1.25 153.838,131.283 v1(154.003,131.448)
  Top Layer w0.254: U6.17 U5.17
  Bottom Layer w0.216: U6.17 98.724,129.385 152.635,129.385 154.003,130.753 v1(154.003,131.448)
RGA2: U1.26 U5.16 U6.16 | length 61.8
  Top Layer w0.216: U1.26 153.438,132.021 v1(153.608,132.191)
  Top Layer w0.254: U6.16 U5.16
  Bottom Layer w0.216: U6.16 100.896,129.753 152.482,129.753 153.416,130.687 153.416,131.999 v1(153.608,132.191)
RGA3: U1.27 U5.15 U6.15 | length 59.9
  Top Layer w0.216: U1.27 153.038,132.699 v1(153.227,132.888)
  Top Layer w0.254: U6.15 U5.15
  Bottom Layer w0.216: U6.15 103.067,130.122 152.329,130.122 153.035,130.827 153.035,132.696 v1(153.227,132.888)
RGA4: U1.28 U5.14 U6.14 | length 57.9
  Top Layer w0.216: U1.28 152.638,133.376 v1(152.705,133.443)
  Top Layer w0.254: U6.14 U5.14
  Bottom Layer w0.216: U6.14 103.886,131.208 104.604,130.49 152.063,130.49 152.654,131.081 152.654,133.392 v1(152.705,133.443)
RGA5: U1.36 U5.13 U6.13 | length 53
  Top Layer w0.216: U5.13 106.426,136.161 108.737,138.472 143.244,138.472 147.72,133.997 147.72,133.475 149.438,131.757 U1.36
  Top Layer w0.254: U6.13 U5.13
RGA6: U1.37 U5.12 U6.12 | length 49.9
  Top Layer w0.216: U5.12 108.966,136.542 110.528,138.104 143.092,138.104 147.352,133.844 147.352,133.322 149.038,131.636 U1.37
  Top Layer w0.254: U6.12 U5.12
RGA7: U1.38 U5.11 U6.11 | length 46.6
  Top Layer w0.216: U5.11 111.506,136.542 112.7,137.736 142.939,137.736 146.808,133.867 146.808,133.855 146.984,133.679 146.984,133.17 148.638,131.515 U1.38
  Top Layer w0.254: U6.11 U5.11
RGA8: U1.39 U5.10 U6.10 | length 43.2
  Top Layer w0.216: U5.10 114.046,136.415 114.998,137.368 142.774,137.368 146.615,133.527 146.615,133.017 148.238,131.395 U1.39
  Top Layer w0.254: U6.10 U5.10
SWCLK: H1.3 U1.33 | length 15.6
  Top Layer w0.2: v1(149.741,133.502) 149.953,133.502 150.638,132.817 U1.33
  Bottom Layer w0.25: v1(149.741,133.502) 150.368,134.129 155.194,134.129 157.226,132.097 159.131,132.097 H1.3@160.02,131.208
SWDIO: H1.1 U1.34 | length 16.9
  Top Layer w0.2: v1(149.098,134.002) 149.098,133.748 149.184,133.662 149.184,133.271 149.51,132.945 149.901,132.945 150.238,132.608 U1.34
  Bottom Layer w0.25: v1(149.098,134.002) 149.418,134.002 149.947,134.531 155.361,134.531 155.89,134.002 157.861,134.002 160.02,136.161 H1.1@160.02,136.288
USB_DM: U1.66 USB1.5 USB1.7 | length 7.2
  Top Layer w0.2: USB1.5 146.304,116.704 146.304,117.365 146.427,117.488 146.556,117.488 146.561,117.494 147.07,117.494 147.076,117.488 147.316,117.488 ; USB1.7 147.316,117.488 ; U1.66 149.838,118.74 148.971,117.873 147.701,117.873 147.316,117.488
USB_DP: U1.67 USB1.6 USB1.8 | length 7.9
  Top Layer w0.2: USB1.6 146.816,115.964 146.939,115.841 147.701,115.841 147.828,115.968 147.828,116.68 USB1.8 147.816,117.386 147.95,117.521 149.117,117.521 150.238,118.642 U1.67
VCC: C17.2 C18.2 U3.3 U4.3 U5.19 U6.19 | length 7.5
  Top Layer w0.8: C17.2 95.758,128.287 ; C18.2 112.395,128.541
VCC18: C5.1 C7.1 C10.1 C13.1 C19.2 U1.10 U1.32 U1.51 U4.2 U4.4 | length 90.4
  Top Layer w0.2: v1(142.666,124.051) 142.666,124.057 143.648,125.039 U1.51 ; v1(150.858,133.385) 151.038,133.205 U1.32 ; U1.10 159.785,125.039 v1(159.809,125.063) ; C10.1@161.48,125.114 C10.1@161.544,125.177 ; C5.1 162.244,122.129 163.117,123.002 163.117,123.946 162.013,125.05 C10.1
  Top Layer w0.4: v1(159.809,125.063) C10.1@161.43,125.063
  Top Layer w0.5: C7.1 142.457,123.842 v1(142.666,124.051) ; C13.1 148.779,134.891 149.352,134.891 v1(150.858,133.385)
  Top Layer w1: U4.4 U4.2 109.793,125.493 C19.2
  Inner2 w1: 109.855,125.493 111.297,124.051 113.221,124.051 113.396,124.226 114.188,124.226 114.363,124.051 v1(142.666,124.051) 144.862,124.051 150.858,130.047 150.858,130.972 ; v1(150.858,133.385) 150.858,130.972 ; v1(159.809,125.063) 156.767,125.063 150.858,130.972
  other v1: 97.155,122.191 101.282,122.209 103.632,122.191 105.445,122.191 98.806,122.235 101.092,123.207 102.1,123.207 103.114,123.207 97.065,123.989 98.801,123.989 100.331,123.989 103.696,123.989 105.445,124.604 100.331,124.933 109.6,125.049 97.069,125.747 98.806,125.747 100.33,125.747 109.601,125.747 110.236,125.747
VCC33: C1.2 C2.2 C6.1 C8.2 C9.1 C11.2 C12.1 C14.2 C15.1 C16.2 R1.2 R9.2 U1.5 U1.15 U1.24 U1.29 U1.35 U1.41 U1.50 U1.59 U1.60 U1.61 U1.64 U1.68 U1.69 U1.76 U2.8 U3.2 U3.4 | length 57.9
  Top Layer w0.2: v1(142.752,125.185) 143.296,125.185 143.55,125.439 U1.50 ; v1(145.257,121.652) 145.827,121.652 ; C15.1 145.288,129.303 145.552,129.039 U1.41 ; U1.60 146.04,121.439 145.827,121.652 ; U1.59 146.014,121.839 145.827,121.652 ; v1(147.066,119.524) 147.574,119.524 147.838,119.788 ; U1.61 147.838,119.788 ; U1.68 150.638,121.02 150.666,121.048 ; U1.69 151.038,120.886 150.876,121.048 150.666,121.048 ; U1.29 152.238,129.719 152.527,129.43 154.051,129.43 154.238,129.617 U1.24 154.238,130.895 154.56,131.217 154.56,132.362 v1(154.726,132.528) ; U1.76 v1(153.838,121.175) ; U1.15 158.137,127.039 v1(158.347,127.249) ; C6.1 164.601,122.129 164.911,121.819 R1.2 ; R9.2 v1(169.746,135.263) ; 147.838,119.788 148.102,119.524 148.844,119.524 149.038,119.718 U1.64 149.024,120.346 149.024,120.974 149.098,121.048 150.666,121.048
  Top Layer w0.216: v1(148.452,133.571) 148.452,133.494 149.361,132.585 149.372,132.585 149.838,132.119 U1.35 ; U1.5 157.938,123.039 157.985,123.086 158.451,123.086 159.003,122.534 159.003,122.475 v1(158.979,122.452)
  Top Layer w0.25: C11.2 147.066,119.081 v1(147.066,119.524)
  Top Layer w0.4: U2.8 156.464,111.015 v1(156.591,110.888) ; C12.1 v1(159.766,118.7) ; C6.1 v1(163.83,123.08) ; C1.2 166.816,112.477 v1(167.132,112.793)
  Top Layer w0.5: C2.2 142.444,125.493 v1(142.752,125.185) ; C9.1 144.907,121.302 v1(145.257,121.652) ; v1(158.347,127.249) 158.84,127.249 159.332,127.741 C8.2@159.332,127.894
  Top Layer w0.8: v1(92.964,125.493) 92.714,125.243 v1(92.714,124.668) 93.017,124.971 93.486,124.971 ; C15.1 146.03,130.889 v1(146.196,131.055) ; v1(154.726,132.528) 154.726,132.704 C14.2
  Top Layer w1: U3.4 U3.2 v1(92.964,125.493) ; 93.486,124.971 93.788,124.669 C16.2
  other v1: 83.185,120.794 85.344,120.794 88.773,120.794 80.899,120.859 78.232,120.88 88.773,122.826 84.328,123.08 85.213,123.08 86.048,123.08 78.221,123.308 80.899,123.308 83.502,123.9 86.741,123.969 88.773,124.644 83.502,124.77 83.502,125.62 78.232,125.747 80.899,125.747
pads on no net: U1.63 U1.65 USB1.2 USB1.3 USB1.4 USB1.9 USB1.10 USB1.11 X1.5 X1.6 X1.11 X1.12 X1.13 X1.14 X1.15 X2.2 X2.4

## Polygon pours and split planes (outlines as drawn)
VCC33 on Bottom Layer (solid, remove dead copper, pour order 4): 90.156,128.108 95.758,128.108 95.758,120.413 90.156,120.413
VCC18 on Bottom Layer (solid, remove dead copper, pour order 6): 106.53,127.056 117.53,127.056 117.53,120.413 106.53,120.413
GND on Top Layer (solid, remove dead copper, pour order 2): 147.616,128.89 155.448,128.89 155.448,121.429 147.616,121.429
GND on Bottom Layer (solid, remove dead copper, pour order 8): 147.574,130.149 157.037,130.149 157.037,120.921 147.574,120.921
VCC on Top Layer (solid, remove dead copper, pour order 0): 89.816,135.526 92.71,135.526 92.71,130.7 112.903,130.7 112.903,127.652 89.816,127.652
VCC33 on Inner2 (solid, remove dead copper): 180.302,109.083 180.721,139.082 76.274,139.139 76.274,109.311
GND on Inner1 (solid, remove dead copper): 76.274,139.139 180.721,139.082 180.594,108.976 76.274,109.311

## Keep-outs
Board Outline Layer:
  lines w0.254: 76.274,109.237 76.274,139.139 158.242,139.115 161.239,137.431 176.274,137.431 176.274,109.237 76.274,109.237

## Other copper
Top Layer:
  drawing of 247 lines, arcs and shapes, not listed
Inner2:
  region net VCC18: 96.774,127.056 105.791,127.056 105.791,121.937 96.774,121.937
  region net VCC18: 105.664,126.04 111.633,126.04 111.633,123.207 105.664,123.207
Bottom Layer:
  region net VCC18: 96.393,127.056 107.188,127.056 107.188,120.413 96.393,120.413
  region net VCC33: 77.724,128.108 90.424,128.108 90.424,120.413 77.724,120.413
  region net SWCLK: 159.105,131.946 159.473,131.932 159.507,131.904 159.545,131.882 159.588,131.865 159.634,131.853 159.682,131.845 159.733,131.84 159.84,131.838 160.059,131.843 160.162,131.839 160.21,131.833 160.254,131.823 159.129,131.078 159.153,131.211 159.184,131.333 159.214,131.446 159.236,131.552 159.241,131.603 159.243,131.653 159.238,131.702 159.228,131.751 159.21,131.799 159.184,131.848 159.15,131.897
  region net SWDIO: 159.15,135.114 158.987,135.305 ccw(c158.457,135.703) 159.12,135.703 159.547,135.247 ccw(c159.547,134.584)
  region net RGA4: 104.399,130.848 103.913,131.029 ccw(c103.569,130.571) 103.569,131.143 104.104,131.143 104.236,131.143 ccw(c104.828,131.277)
  region net RGA3: 102.176,131.165 102.024,131.013 ccw(c101.709,130.698) 101.696,131.143 101.795,131.242 101.947,131.394 102.046,131.493 ccw(c102.491,131.48)
  region net RGA2: 99.636,131.165 99.484,131.013 ccw(c99.169,130.698) 99.156,131.143 99.255,131.242 99.407,131.394 99.506,131.493 ccw(c99.951,131.48)
  region net RGA1: 97.096,131.165 96.944,131.013 ccw(c96.629,130.698) 96.616,131.143 96.715,131.242 96.867,131.394 96.966,131.493 ccw(c97.411,131.48)
  region net R0: 89.476,131.165 89.324,131.013 ccw(c89.009,130.698) 88.996,131.143 89.095,131.242 89.247,131.394 89.346,131.493 ccw(c89.791,131.48)
  region net R1: 86.936,131.165 86.784,131.013 ccw(c86.469,130.698) 86.456,131.143 86.555,131.242 86.707,131.394 86.806,131.493 ccw(c87.251,131.48)
  region net R2: 84.396,131.165 84.244,131.013 ccw(c83.929,130.698) 83.916,131.143 84.015,131.242 84.167,131.394 84.266,131.493 ccw(c84.711,131.48)
  region net R3: 81.856,131.165 81.704,131.013 ccw(c81.389,130.698) 81.376,131.143 81.475,131.242 81.627,131.394 81.726,131.493 ccw(c82.171,131.48)
  region net B0: 79.294,131.177 79.152,131.035 ccw(c78.885,130.767) 78.836,131.143 78.94,131.247 79.082,131.389 79.186,131.493 ccw(c79.562,131.444)
  region net B1: 79.294,115.937 79.152,115.795 ccw(c78.885,115.527) 78.836,115.903 78.94,116.007 79.082,116.149 79.186,116.253 ccw(c79.562,116.205)
  region net B2: 81.834,115.937 81.692,115.795 ccw(c81.425,115.527) 81.376,115.903 81.48,116.007 81.622,116.149 81.726,116.253 ccw(c82.102,116.205)
  region net B3: 84.374,115.937 84.232,115.795 ccw(c83.965,115.527) 83.916,115.903 84.02,116.007 84.162,116.149 84.266,116.253 ccw(c84.642,116.205)
  region net G0: 86.936,115.925 86.784,115.773 ccw(c86.469,115.458) 86.456,115.903 86.555,116.002 86.707,116.154 86.806,116.253 ccw(c87.251,116.24)
  region net G1: 89.476,115.925 89.324,115.773 ccw(c89.009,115.458) 88.996,115.903 89.095,116.002 89.247,116.154 89.346,116.253 ccw(c89.791,116.24)
  region net G2: 92.016,115.925 91.864,115.773 ccw(c91.549,115.458) 91.536,115.903 91.635,116.002 91.787,116.154 91.886,116.253 ccw(c92.331,116.24)
  region net G3: 94.556,115.925 94.404,115.773 ccw(c94.089,115.458) 94.076,115.903 94.175,116.002 94.327,116.154 94.426,116.253 ccw(c94.871,116.24)
  region net R0: 154.116,119.456 154.331,119.456 154.334,119.423 154.342,119.393 154.354,119.366 154.369,119.34 154.408,119.292 154.452,119.242 153.995,119.242 154.039,119.292 154.078,119.34 154.093,119.366 154.105,119.393 154.113,119.423
  region net G1: 157.912,120.888 157.912,121.104 157.944,121.107 157.974,121.114 158.001,121.126 158.027,121.142 158.076,121.18 158.125,121.225 158.125,120.767 158.076,120.811 158.027,120.85 158.001,120.866 157.974,120.878 157.944,120.885
  region net G2: 158.003,121.65 158.003,121.866 158.036,121.869 158.065,121.876 158.093,121.888 158.119,121.904 158.167,121.942 158.217,121.987 158.217,121.529 158.167,121.573 158.119,121.612 158.093,121.628 158.065,121.64 158.036,121.647
  region net SWDIO: 149.418,134.127 149.418,133.877 149.393,133.875 149.375,133.868 149.362,133.858 149.351,133.845 149.332,133.811 149.318,133.793 149.3,133.773 149.3,134.231 149.318,134.211 149.332,134.193 149.351,134.159 149.362,134.146 149.375,134.136 149.393,134.129
  region net BLANK: 156.191,131.78 155.975,131.78 155.971,131.797 155.96,131.813 155.926,131.842 155.886,131.869 155.854,131.895 156.312,131.895 156.28,131.869 156.24,131.842 156.206,131.813 156.195,131.797
  region net CDAC: 157.861,130.6 157.861,130.8 157.894,130.803 157.92,130.811 157.941,130.824 157.96,130.84 157.995,130.882 158.04,130.929 158.04,130.471 157.995,130.519 157.96,130.56 157.941,130.576 157.92,130.589 157.894,130.597
  region net B3: 160.32,123.163 160.179,123.304 160.201,123.33 160.217,123.357 160.227,123.385 160.232,123.415 160.237,123.477 160.239,123.546 160.562,123.223 160.493,123.221 160.431,123.216 160.402,123.21 160.374,123.2 160.347,123.185
  region net CSI_CLK_P: 167.868,132.471 167.868,132.721 167.898,132.724 167.927,132.73 167.982,132.754 168.035,132.787 168.082,132.825 168.082,132.368 168.035,132.406 167.982,132.439 167.927,132.462 167.898,132.469
  region net CSI_CLK_N: 167.92,131.709 167.92,131.959 167.949,131.962 167.978,131.968 168.034,131.992 168.086,132.025 168.133,132.063 168.133,131.606 168.086,131.644 168.034,131.677 167.978,131.7 167.949,131.707
  region net CSI_CLK_P: 168.891,124.602 168.891,124.352 168.862,124.35 168.833,124.343 168.777,124.32 168.725,124.286 168.678,124.248 168.678,124.706 168.725,124.668 168.777,124.634 168.833,124.611 168.862,124.604
  region net CSI_CLK_N: 168.891,123.577 168.891,123.327 168.862,123.325 168.833,123.318 168.777,123.294 168.725,123.261 168.678,123.223 168.678,123.681 168.725,123.643 168.777,123.609 168.833,123.586 168.862,123.579

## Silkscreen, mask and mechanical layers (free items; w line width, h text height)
Top Silkscreen Layer:
  region: 113.739,130.065 118.739,130.065 118.739,125.065 113.739,125.065
Bottom Silkscreen Layer:
  text "My signal on the line, / needs to waste a little time. / Through the trace it has to wiggle, / for an 833ps jiggle." at 171.143,130.7 h1 r90
  text "A passion project.  / Commercial use? / Please support me: / paypal.me/ClaudeSchwarz1337" at 139.827,121.302 h1.5
Top Solder Mask Layer:
  drawing of 35 lines, arcs and shapes, not listed
  text "Framethrower / OCS/ECS / Revision 1.0" at 124.587,121.937 h1.5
